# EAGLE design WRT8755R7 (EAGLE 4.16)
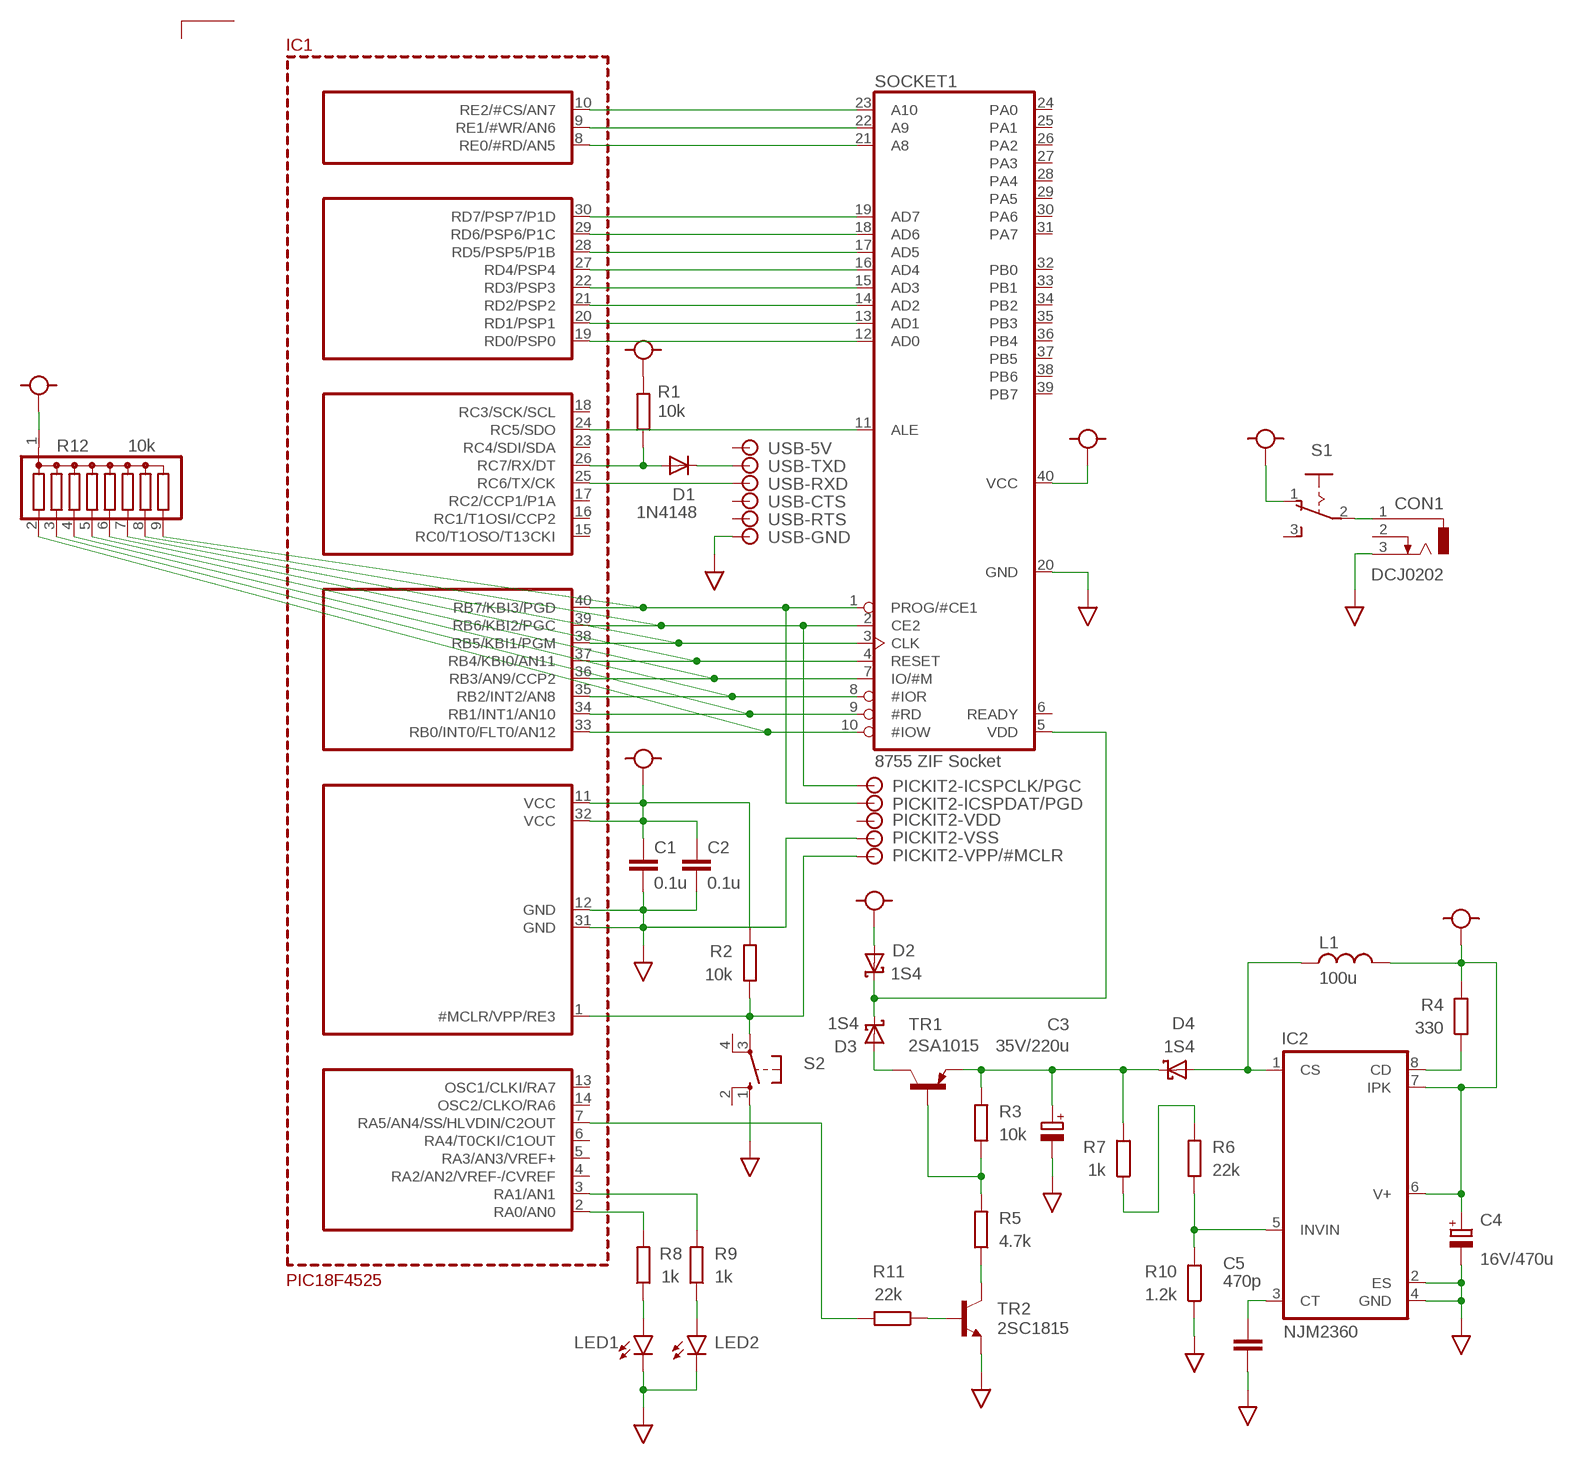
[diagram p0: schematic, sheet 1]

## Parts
C1  0.1u  C-CERAMIC  [C025-025X050]
C2  0.1u  C-CERAMIC  [C025-025X050]
C3  35V/220u  C-CHEMICAL  [C-CHEMICAL]
C4  16V/470u  C-CHEMICAL  [C-CHEMICAL]
C5  470p  C-CERAMIC  [C025-025X050]
CON1  DCJ0202  [DCJ0202]
D1  1N4148  1S1588  [DO41-10]
D2  1S4  [DO41-10]
D3  1S4  [DO41-10]
D4  1S4  [DO41-10]
IC1  PIC18F4525  [DIL40]
IC2  NJM2360  NJM2360A  [DIL08]
L1  100u  L47  [L47]
LED1  LED3MM  [LED3MM]
LED2  LED3MM  [LED3MM]
PICKIT2-  PICKIT2  [PICKIT2]
R1  10k  R1/8W  [0207/10]
R2  10k  R1/8W  [0207/10]
R3  10k  R1/8W  [0207/10]
R4  330  R1/8W  [0207/10]
R5  4.7k  R1/8W  [0207/10]
R6  22k  R1/8W  [0207/10]
R7  1k  R1/8W  [0207/10]
R8  1k  R1/8W  [0207/10]
R9  1k  R1/8W  [0207/10]
R10  1.2k  R1/8W  [0207/10]
R11  22k  R1/8W  [0207/10]
R12  10k  G08R  [SIL9]
S1  255SB  [255SB]
S2  SW-TACT  [B3F-10XX]
SOCKET1  8755 ZIF Socket  8755-ZIF  [DIL40-ZIF]
TR1  2SA1015  TR-PNP  [TO92-BCE]
TR2  2SC1815  TR-NPN  [TO92-BCE]
USB-  TTL-232R-5V  [TTL-232R-5V]

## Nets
25V: C3.+ D4.C R3.2 R7.2 TR1.E
A8: IC1.8(RE0/#RD/AN5) SOCKET1.21(A8)
A9: IC1.9(RE1/#WR/AN6) SOCKET1.22(A9)
A10: IC1.10(RE2/#CS/AN7) SOCKET1.23(A10)
AD0: IC1.19(RD0/PSP0) SOCKET1.12(AD0)
AD1: IC1.20(RD1/PSP1) SOCKET1.13(AD1)
AD2: IC1.21(RD2/PSP2) SOCKET1.14(AD2)
AD3: IC1.22(RD3/PSP3) SOCKET1.15(AD3)
AD4: IC1.27(RD4/PSP4) SOCKET1.16(AD4)
AD5: IC1.28(RD5/PSP5/P1B) SOCKET1.17(AD5)
AD6: IC1.29(RD6/PSP6/P1C) SOCKET1.18(AD6)
AD7: IC1.30(RD7/PSP7/P1D) SOCKET1.19(AD7)
CE1: IC1.40(RB7/KBI3/PGD) PICKIT2-.4 R12.9 SOCKET1.1(PROG/#CE1)
CE2: IC1.39(RB6/KBI2/PGC) PICKIT2-.5 R12.8 SOCKET1.2(CE2)
CLK: IC1.38(RB5/KBI1/PGM) R12.7 SOCKET1.3(CLK)
GND: C1.2 C2.2 C3.- C4.- C5.2 CON1.3 IC1.12(GND) IC1.31(GND) IC2.2(ES) IC2.4(GND) LED1.K(C) LED2.K(C) PICKIT2-.3 R10.1 S2.1(S) SOCKET1.20(GND) TR2.E USB-.1
IO/M: IC1.36(RB3/AN9/CCP2) R12.5 SOCKET1.7(IO/#M)
IOR: IC1.35(RB2/INT2/AN8) R12.4 SOCKET1.8(#IOR)
IOW: IC1.33(RB0/INT0/FLT0/AN12) R12.2 SOCKET1.10(#IOW)
N$1: IC1.2(RA0/AN0) R8.2
N$2: IC1.7(RA5/AN4/SS/HLVDIN/C2OUT) R11.2
N$5: R11.1 TR2.B
N$6: R5.1 TR2.C
N$7: R3.1 R5.2 TR1.B
N$9: D3.A TR1.C
N$11: IC1.3(RA1/AN1) R9.2
N$14: IC1.1(#MCLR/VPP/RE3) PICKIT2-.1 R2.1 S2.3(P)
N$17: LED1.A R8.1
N$18: LED2.A R9.1
N$23: D1.A IC1.26(RC7/RX/DT) R1.1
N$29: IC1.24(RC5/SDO) SOCKET1.11(ALE)
N$30: D1.C USB-.4
N$31: IC1.25(RC6/TX/CK) USB-.5
N$36: CON1.1 S1.2(P)
N$37: IC2.8(CD) R4.1
N$38: D4.A IC2.1(CS) L1.2
N$39: C5.1 IC2.3(CT)
N$41: IC2.5(INVIN) R6.1 R10.2
N$42: R6.2 R7.1
RD: IC1.34(RB1/INT1/AN10) R12.3 SOCKET1.9(#RD)
RESET: IC1.37(RB4/KBI0/AN11) R12.6 SOCKET1.4(RESET)
VCC: C1.1 C2.1 C4.+ D2.A IC1.11(VCC) IC1.32(VCC) IC2.6(V+) IC2.7(IPK) L1.1 R1.2 R2.2 R4.2 R12.1 S1.1(O) SOCKET1.40(VCC)
VDD: D2.C D3.C SOCKET1.5(VDD)
Unconnected: CON1.2 IC1.4(RA2/AN2/VREF-/CVREF) IC1.5(RA3/AN3/VREF+) IC1.6(RA4/T0CKI/C1OUT) IC1.13(OSC1/CLKI/RA7) IC1.14(OSC2/CLKO/RA6) IC1.15(RC0/T1OSO/T13CKI) IC1.16(RC1/T1OSI/CCP2) IC1.17(RC2/CCP1/P1A) IC1.18(RC3/SCK/SCL) IC1.23(RC4/SDI/SDA) PICKIT2-.2 PICKIT2-.6 S1.3(S) S2.2(S1) S2.4(P1) SOCKET1.6(READY) SOCKET1.24(PA0) SOCKET1.25(PA1) SOCKET1.26(PA2) SOCKET1.27(PA3) SOCKET1.28(PA4) SOCKET1.29(PA5) SOCKET1.30(PA6) SOCKET1.31(PA7) SOCKET1.32(PB0) SOCKET1.33(PB1) SOCKET1.34(PB2) SOCKET1.35(PB3) SOCKET1.36(PB4) SOCKET1.37(PB5) SOCKET1.38(PB6) SOCKET1.39(PB7) USB-.2 USB-.3 USB-.6

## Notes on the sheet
- IC1
- PIC18F4525

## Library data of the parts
C1 C2 C5 = olimex-devices:C-CERAMIC: Ceramic Conenser
C3 C4 = olimex-devices:C-CHEMICAL
CON1 = olimex-devices:DCJ0202: DC POWER JACK Source: DCJ0202.pdf
D1 = olimex-devices:1S1588: Small Signal Diode
D2-D4 = olimex-devices:1S4
IC1 = olimex-devices:PIC18F4525
IC2 = olimex-devices:NJM2360A
L1 = olimex-devices:L47
LED1 LED2 = olimex-devices:LED3MM: LED
PICKIT2- = olimex-devices:PICKIT2
R1-R11 = olimex-devices:R1/8W: Carbon Resistor
R12 = olimex-devices:G08R: SIL RESISTOR
S1 = olimex-devices:255SB: SLIDING SWITCH distributor Buerklin, 11G810
S2 = olimex-devices:SW-TACT: Tact Switch (Small)
SOCKET1 = olimex-devices:8755-ZIF
TR1 = olimex-devices:TR-PNP: Transistor for Small Signal
TR2 = olimex-devices:TR-NPN: Transistor for Small Signal
USB- = olimex-devices:TTL-232R-5V

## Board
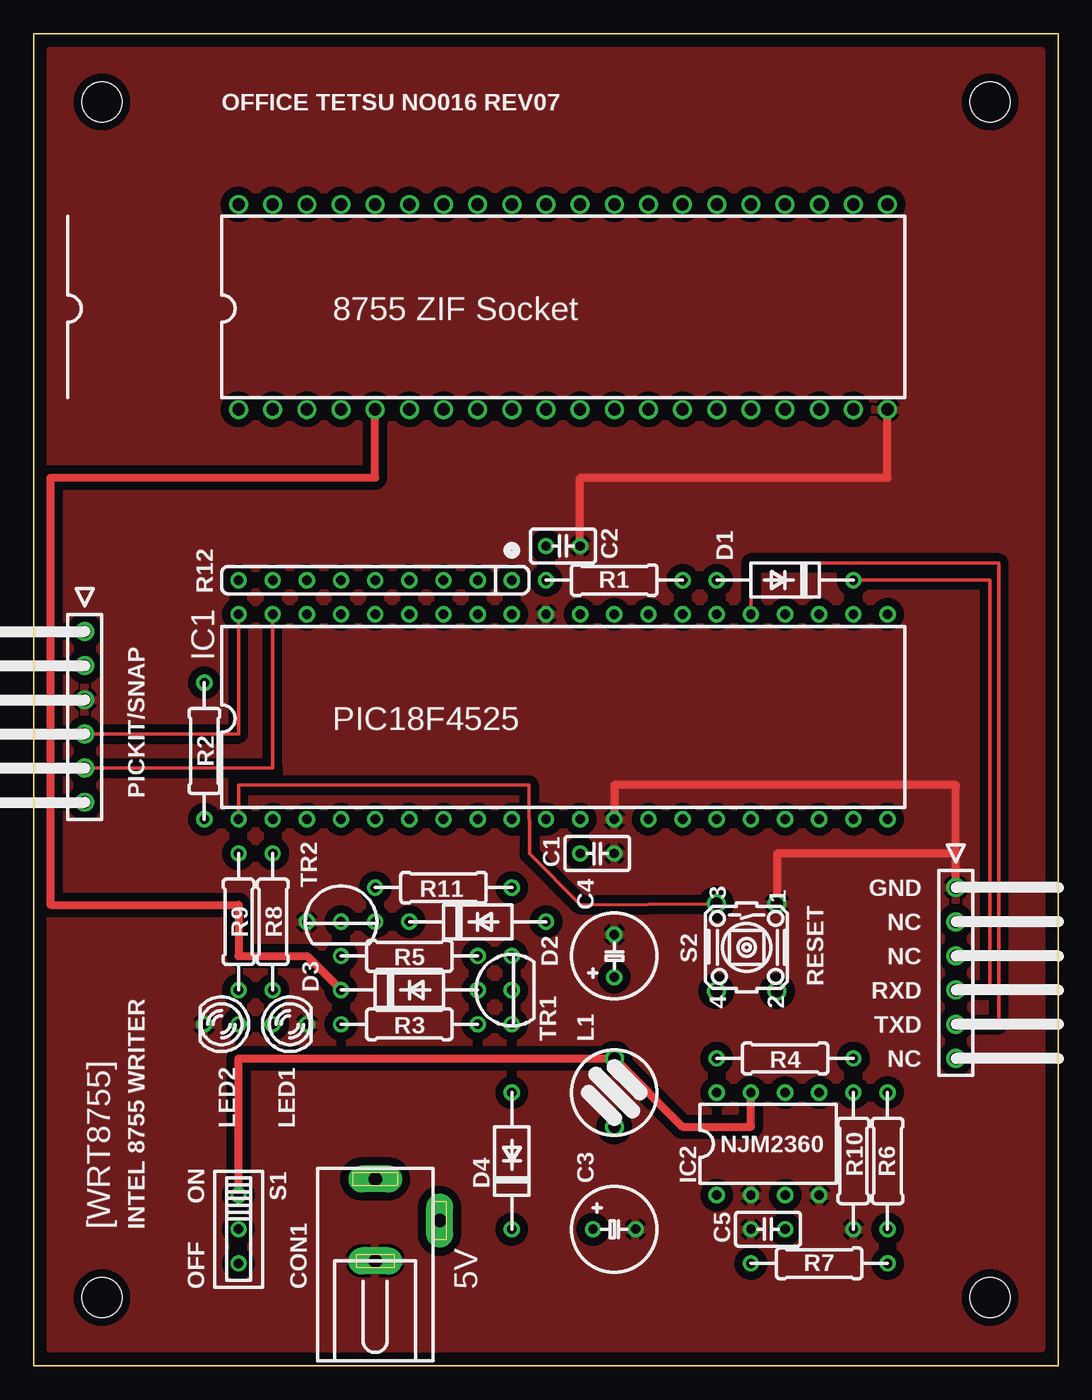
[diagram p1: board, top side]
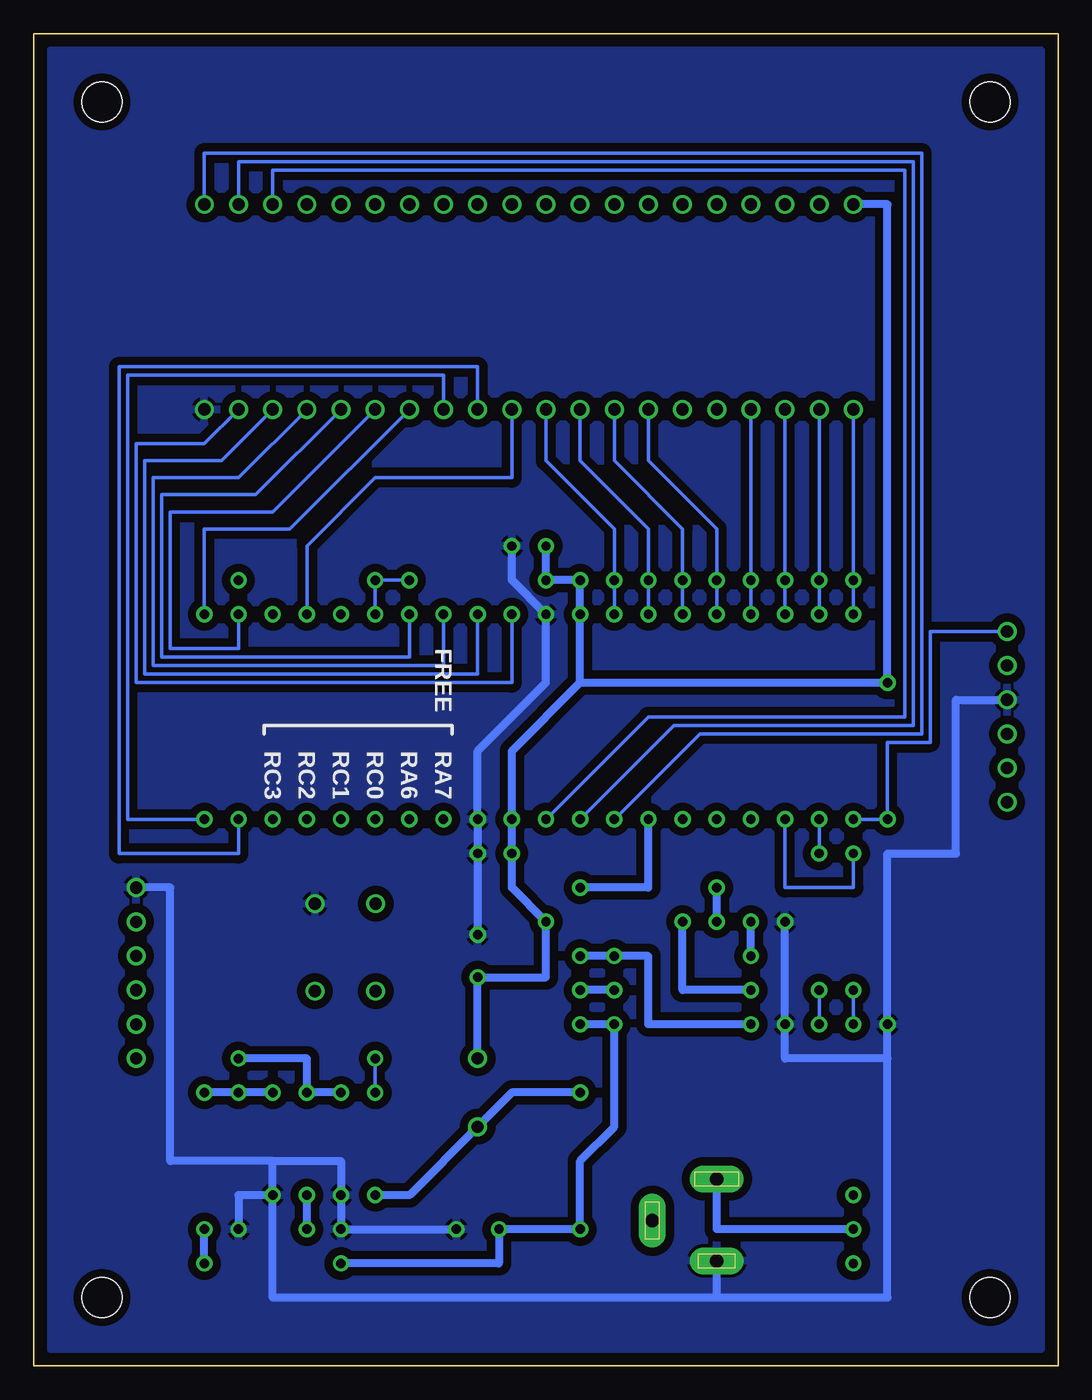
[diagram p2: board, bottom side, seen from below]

Size 76.2 x 99.06 mm. Coordinates in mm from the lower left corner, seen from the top.
Outline: 0,99.06 0,0 76.2,0 76.2,99.06 0,99.06
Copper layers (1*16): Top 0.035mm / dielectric 1.5mm / Bottom 0.035mm
Design rules "SeeedStudio": minimum track width 6mil, minimum drill 12mil, track to track 6mil, track to pad 6mil, pad to pad 6mil, via to via 6mil, smd to smd 0mil, copper to edge 10mil, drill to drill 10mil, minimum pad ring 10mil, minimum via ring 6mil, stop-mask expansion 2mil, vias tented up to drill 25mil, thermal gap 10mil
Holes 3 mm at 5.08,5.08 5.08,93.98 71.12,5.08 71.12,93.98

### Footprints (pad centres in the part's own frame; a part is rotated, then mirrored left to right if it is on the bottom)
C025-025X050 = drill 0.7 round: 1 -1.27,0; 2 1.27,0
C-CHEMICAL = drill 0.7 round: + -1.587,0; - 1.587,0
DCJ0202 = drill 1 pad 2 long: 1 0,3.1; 2 4.8,0; 3 0,-3
DO41-10 = drill 0.7 round: A 5.08,0; C -5.08,0
DIL40 = drill 0.7 round: 1 -24.13,-7.62; 2 -21.59,-7.62; 3 -19.05,-7.62; 4 -16.51,-7.62; 5 -13.97,-7.62; 6 -11.43,-7.62; 7 -8.89,-7.62; 8 -6.35,-7.62; 9 -3.81,-7.62; 10 -1.27,-7.62; 11 1.27,-7.62; 12 3.81,-7.62; 13 6.35,-7.62; 14 8.89,-7.62; 15 11.43,-7.62; 16 13.97,-7.62; 17 16.51,-7.62; 18 19.05,-7.62; 19 21.59,-7.62; 20 24.13,-7.62; 21 24.13,7.62; 22 21.59,7.62; 23 19.05,7.62; 24 16.51,7.62; 25 13.97,7.62; 26 11.43,7.62; 27 8.89,7.62; 28 6.35,7.62; 29 3.81,7.62; 30 1.27,7.62; 31 -1.27,7.62; 32 -3.81,7.62; 33 -6.35,7.62; 34 -8.89,7.62; 35 -11.43,7.62; 36 -13.97,7.62; 37 -16.51,7.62; 38 -19.05,7.62; 39 -21.59,7.62; 40 -24.13,7.62
DIL08 = drill 0.7 round: 1 -3.81,-3.81; 2 -1.27,-3.81; 3 1.27,-3.81; 4 3.81,-3.81; 5 3.81,3.81; 6 1.27,3.81; 7 -1.27,3.81; 8 -3.81,3.81
L47 = drill 0.9 round: 1 0,2.54; 2 0,-2.54
LED3MM = drill 0.7 round: A -1.27,0; K 1.27,0
PICKIT2 = drill 0.9 round: 1 5.08,0; 2 2.54,0; 3 0,0; 4 -2.54,0; 5 -5.08,0; 6 -7.62,0
0207/10 = drill 0.7 round: 1 -5.08,0; 2 5.08,0
SIL9 = drill 0.7 round: 1 -10.16,0; 2 -7.62,0; 3 -5.08,0; 4 -2.54,0; 5 0,0; 6 2.54,0; 7 5.08,0; 8 7.62,0; 9 10.16,0
255SB = drill 0.7 round: 1 -2.54,0; 2 0,0; 3 2.54,0
B3F-10XX = drill 0.9 round: 1 -3.251,2.261; 2 3.251,2.261; 3 -3.251,-2.261; 4 3.251,-2.261
DIL40-ZIF = drill 0.9 round: 1 -24.13,-7.62; 2 -21.59,-7.62; 3 -19.05,-7.62; 4 -16.51,-7.62; 5 -13.97,-7.62; 6 -11.43,-7.62; 7 -8.89,-7.62; 8 -6.35,-7.62; 9 -3.81,-7.62; 10 -1.27,-7.62; 11 1.27,-7.62; 12 3.81,-7.62; 13 6.35,-7.62; 14 8.89,-7.62; 15 11.43,-7.62; 16 13.97,-7.62; 17 16.51,-7.62; 18 19.05,-7.62; 19 21.59,-7.62; 20 24.13,-7.62; 21 24.13,7.62; 22 21.59,7.62; 23 19.05,7.62; 24 16.51,7.62; 25 13.97,7.62; 26 11.43,7.62; 27 8.89,7.62; 28 6.35,7.62; 29 3.81,7.62; 30 1.27,7.62; 31 -1.27,7.62; 32 -3.81,7.62; 33 -6.35,7.62; 34 -8.89,7.62; 35 -11.43,7.62; 36 -13.97,7.62; 37 -16.51,7.62; 38 -19.05,7.62; 39 -21.59,7.62; 40 -24.13,7.62
TO92-BCE = drill 0.7 round: B 2.54,0; C 0,0; E -2.54,0
TTL-232R-5V = drill 0.9 round: 1 -6.35,0; 2 -3.81,0; 3 -1.27,0; 4 1.27,0; 5 3.81,0; 6 6.35,0

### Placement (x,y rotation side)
C1  41.91,38.1 0 top
C2  39.37,60.96 0 top
C3  43.18,10.16 0 top
C4  43.18,30.48 90 top
C5  54.61,10.16 180 top
CON1  25.4,10.79 0 top
D1  55.88,58.42 180 top
D2  33.02,33.02 0 top
D3  27.94,27.94 0 top
D4  35.56,15.24 90 top
IC1  39.37,48.26 0 top
IC2  54.61,16.51 0 top
L1  43.18,20.32 0 top
LED1  19.05,25.4 0 top
LED2  13.97,25.4 180 top
PICKIT2-  3.81,49.53 90 top
R1  43.18,58.42 180 top
R2  12.7,45.72 90 top
R3  27.94,25.4 0 top
R4  55.88,22.86 0 top
R5  27.94,30.48 0 top
R6  63.5,15.24 270 top
R7  58.42,7.62 180 top
R8  17.78,33.02 90 top
R9  15.24,33.02 90 top
R10  60.96,15.24 90 top
R11  30.48,35.56 0 top
R12  25.4,58.42 180 top
S1  15.24,10.16 270 top
S2  53.02,31.11 270 top
SOCKET1  39.37,78.74 0 top
TR1  35.56,27.94 90 top
TR2  22.86,33.02 0 top
USB-  68.58,29.21 270 top

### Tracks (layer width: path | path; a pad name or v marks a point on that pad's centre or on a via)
25V
  Bottom 0.61: R7.2 41.59,7.62 C3.+ D4.C 35.56,15.24 33.02,17.78 R3.2 TR1.E
A8
  Bottom 0.254: IC1.8 26.67,46.99 10.16,46.99 10.16,90.17 63.5,90.17 SOCKET1.21
A9
  Bottom 0.254: IC1.9 28.57,47.62 10.79,47.62 10.79,89.53 60.96,89.53 SOCKET1.22
A10
  Bottom 0.254: IC1.10 30.48,48.26 11.43,48.26 11.43,88.9 58.42,88.9 SOCKET1.23
AD0
  Bottom 0.254: IC1.19 60.96,38.1 69.85,38.1 69.85,74.3 43.18,74.3 SOCKET1.12
AD1
  Bottom 0.254: IC1.20 69.22,40.64 69.22,73.66 45.72,73.66 SOCKET1.13
AD2
  Bottom 0.254: IC1.21 63.5,62.23 57.15,62.23 SOCKET1.14
AD3
  Bottom 0.254: IC1.22 60.96,53.34 66.04,53.34 66.04,63.5 58.42,63.5 SOCKET1.15
AD4
  Bottom 0.254: IC1.27 48.26,52.7 66.67,52.7 66.67,64.77 59.69,64.77 SOCKET1.16
AD5
  Bottom 0.254: IC1.28 45.72,52.07 67.31,52.07 67.31,66.04 60.96,66.04 SOCKET1.17
AD6
  Bottom 0.254: IC1.29 43.18,51.44 67.94,51.44 67.94,67.31 62.23,67.31 SOCKET1.18
AD7
  Bottom 0.254: IC1.30 40.64,50.8 68.58,50.8 68.58,68.58 63.5,68.58 SOCKET1.19
CE1
  Top 0.254: PICKIT2-.4 15.24,46.99 IC1.40
  Bottom 0.254: SOCKET1.1 R12.9 IC1.40
CE2
  Top 0.254: PICKIT2-.5 17.78,44.45 IC1.39
  Bottom 0.254: SOCKET1.2 R12.8 IC1.39
CLK
  Bottom 0.254: SOCKET1.3 R12.7 IC1.38
GND
  Top 0.61: USB-.1 68.58,38.1 | 68.58,38.1 68.58,43.18 43.18,43.18 IC1.12 | S2.1 55.28,38.1 68.58,38.1 | SOCKET1.20 63.5,66.04 40.64,66.04 C2.2
  Bottom 0.61: 12.7,22.86 20.32,22.86 LED1.K TR2.E | 12.7,22.86 LED2.K 12.7,38.1 7.62,38.1 7.62,49.53 PICKIT2-.3 | 12.7,22.86 12.7,5.08 25.4,5.08 | 25.4,5.08 CON1.3 | R10.1 60.96,12.7 IC2.4 | IC2.4 58.42,5.08 25.4,5.08 | 58.42,15.24 53.34,15.24 IC2.2 C5.2 C3.- | IC2.4 58.42,15.24 | 58.42,15.24 66.04,15.24 66.04,35.56 USB-.1 | C4.- C1.2 IC1.12 43.18,45.72 38.1,50.8 IC1.31 40.64,58.42 C2.2
  pour Top (isolate 0.61): 1.27,1.27 1.27,97.79 74.93,97.79 74.93,1.27
  pour Bottom (isolate 0.61): 1.27,1.27 1.27,97.79 74.93,97.79 74.93,1.27
IO/M
  Bottom 0.254: SOCKET1.7 30.48,67.31 25.4,62.23 R12.5 IC1.36
IOR
  Bottom 0.254: SOCKET1.8 33.02,67.31 27.94,62.23 R12.4 IC1.35
IOW
  Bottom 0.254: SOCKET1.10 38.1,67.31 33.02,62.23 R12.2 IC1.33
N$1
  Bottom 0.254: R8.2 IC1.2
N$2
  Bottom 0.61: IC1.7 30.48,35.56 R11.2
N$5
  Bottom 0.61: TR2.B R11.1
N$6
  Bottom 0.61: R5.1 TR2.C
N$7
  Bottom 0.61: R3.1 30.48,25.4 30.48,30.48 R5.2 TR1.B
N$9
  Bottom 0.61: D3.A TR1.C
N$11
  Bottom 0.254: R9.2 15.24,35.56 20.32,35.56 IC1.3
N$14
  Top 0.254: S2.3 40.68,34.29 36.87,38.1 36.83,43.18 15.24,43.18 IC1.1
  Bottom 0.254: IC1.1 R2.1 12.7,46.35 9.53,46.35 9.53,54.61 PICKIT2-.1
N$17
  Bottom 0.254: LED1.A R8.1
N$18
  Bottom 0.254: LED2.A R9.1
N$23
  Bottom 0.254: R1.1 D1.A IC1.26
N$29
  Bottom 0.254: IC1.24 55.88,60.96 50.8,66.04 40.64,66.04 SOCKET1.11
N$30
  Top 0.254: D1.C 71.12,58.42 71.12,27.94 USB-.4
N$31
  Top 0.254: IC1.25 53.34,59.69 71.75,59.69 71.75,25.4 USB-.5
N$36
  Bottom 0.61: S1.2 25.4,10.16 CON1.1
N$37
  Bottom 0.254: IC2.8 R4.1
N$38
  Bottom 0.61: IC2.1 48.26,12.7 L1.2 40.64,20.32 D4.A
N$39
  Bottom 0.61: C5.1 IC2.3
N$41
  Bottom 0.61: R6.1 R10.2 IC2.5
N$42
  Bottom 0.61: R7.1 R6.2
RD
  Bottom 0.254: SOCKET1.9 35.56,67.31 30.48,62.23 R12.3 IC1.34
RESET
  Bottom 0.254: SOCKET1.4 R12.6 IC1.37
VCC
  Top 0.61: S1.1 15.24,22.86 L1.1 48.26,17.78 53.34,17.78 IC2.7
  Bottom 0.61: 35.56,50.8 40.64,45.72 IC1.11 C1.1 40.64,35.56 D2.A 38.1,28.89 C4.+ L1.1 | 35.56,50.8 IC1.32 R12.1 R1.2 C2.1 | 35.56,50.8 R2.2 12.7,86.36 SOCKET1.40 | R4.2 55.88,22.86 IC2.6 IC2.7
VDD
  Top 0.61: D3.C 20.32,30.48 15.24,30.48 15.24,34.29 1.27,34.29 1.27,66.04 25.4,66.04 SOCKET1.5
  Bottom 0.61: D2.C 27.94,27.94 D3.C

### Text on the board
tPlace: OFFICE TETSU NO016 REV07 | PICKIT/SNAP | GND | NC | NC | RXD | RESET | TXD | NC | ON | [WRT8755] | INTEL 8755 WRITER | OFF | 5V
bPlace: FREE | RA7 | RA6 | RC0 | RC1 | RC2 | RC3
